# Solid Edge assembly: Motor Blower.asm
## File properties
Author: CADCIM
Template: ansi assembly.asm
Last saved by: Cadcim
Revision: 3
Application: Solid Edge
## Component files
cover.par
Lower Housing.par
upper housing.par
Blower.par
motorshaft.par
Motor.par
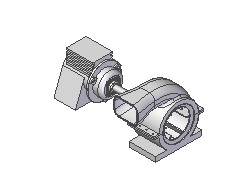
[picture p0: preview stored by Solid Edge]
